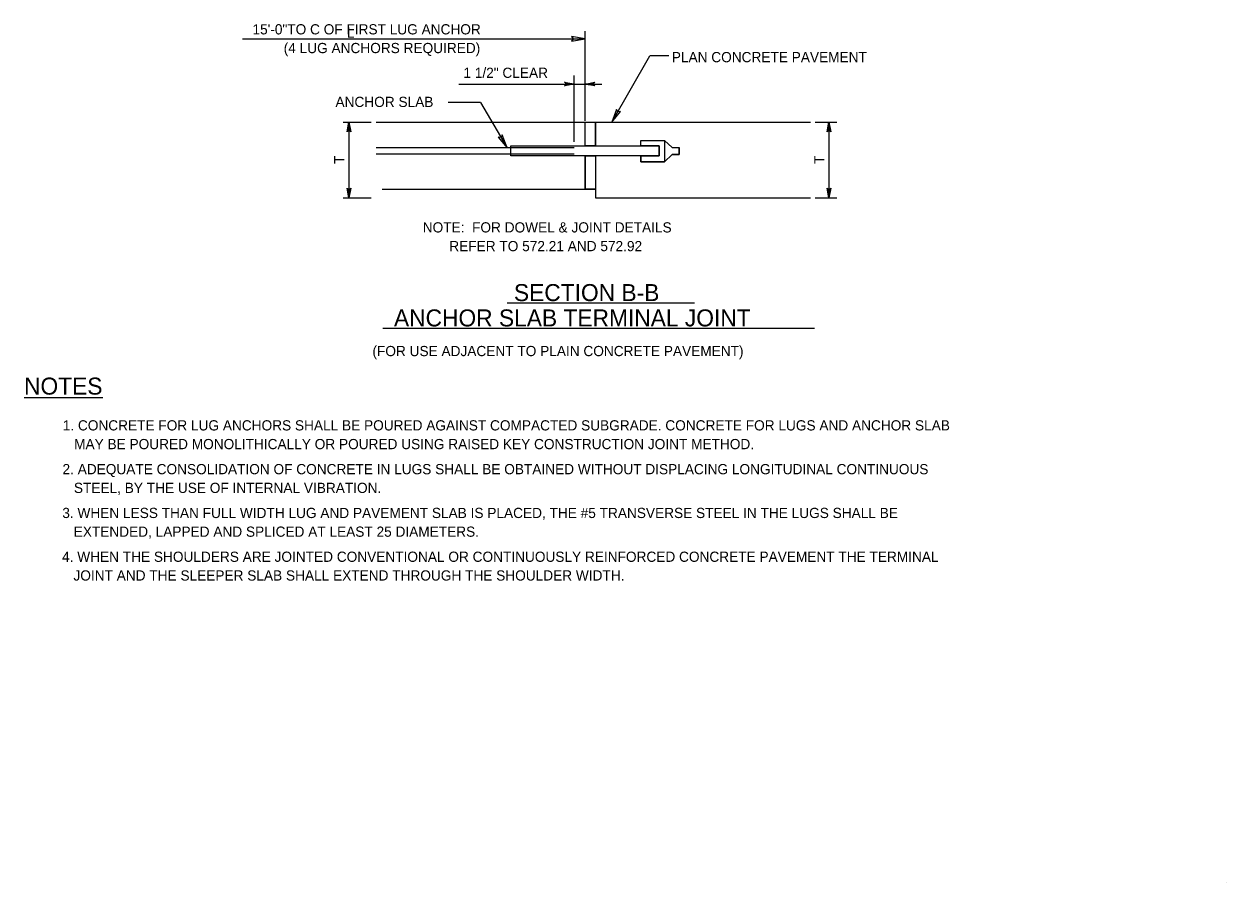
# Model space of a CAD drawing. Extents: x 3.1 to 10.2, y 1.2 to 11.3.
# Drawn here: x 3.1 to 10.16, y 1.24 to 6.28 of the extents above; entities that cross this region are included whole.
import ezdxf

# ---------------------------------------------------------------- set-up
doc = ezdxf.new("R2010")
doc.units = 0
for name, color, linetype in [('DETL-DIMS', 7, 'Continuous'), ('DETL-LINE', 7, 'Continuous'), ('DETL-NOTE', 7, 'Continuous'), ('DETL-TITL', 7, 'Continuous'), ('TTLB-TEXT', 7, 'Continuous')]:
    doc.layers.add(name, color=color, linetype=linetype)

msp = doc.modelspace()

# ---------------------------------------------------------------- linework, layer by layer
at = {"layer": 'DETL-DIMS'}
for p, q in [((6.3939, 5.715), (6.3939, 6.2413)), ((4.3804, 6.1972), (6.3939, 6.1972)), ((6.3939, 6.1972), (6.3141, 6.2105)), ((6.3141, 6.2105), (6.3241, 6.1972)), ((6.3939, 6.1972), (6.3141, 6.2105)), ((6.3141, 6.2105), (6.3241, 6.1972)), ((6.3241, 6.1972), (6.3141, 6.1839)), ((6.3141, 6.1839), (6.3939, 6.1972)), ((6.3241, 6.1972), (6.3141, 6.1839)), ((6.3141, 6.1839), (6.3939, 6.1972)), ((6.5507, 5.7069), (6.7733, 6.0977)), ((6.8851, 6.0977), (6.7733, 6.0977)), ((6.3297, 5.593), (6.3297, 5.9815)), ((5.6524, 5.9317), (6.4911, 5.9317)), ((5.7794, 5.8233), (5.59, 5.8233)), ((5.7794, 5.8233), (5.9351, 5.5578)), ((6.5785, 5.7828), (6.5507, 5.7069)), ((6.5785, 5.7828), (6.5507, 5.7069)), ((6.5507, 5.7069), (6.6017, 5.7697)), ((6.5507, 5.7069), (6.6017, 5.7697)), ((6.5852, 5.7675), (6.5785, 5.7828)), ((6.5852, 5.7675), (6.5785, 5.7828)), ((6.6017, 5.7697), (6.5852, 5.7675)), ((6.6017, 5.7697), (6.5852, 5.7675)), ((4.9721, 5.7069), (5.1367, 5.7069)), ((5.006, 5.7069), (5.006, 5.2638)), ((7.7458, 5.7069), (7.872, 5.7069)), ((7.8262, 5.7069), (7.8262, 5.2638)), ((5.8998, 5.618), (5.8832, 5.6199)), ((5.8832, 5.6199), (5.9351, 5.5578)), ((5.8998, 5.618), (5.8832, 5.6199)), ((5.8832, 5.6199), (5.9351, 5.5578)), ((5.9061, 5.6334), (5.8998, 5.618)), ((5.9061, 5.6334), (5.8998, 5.618)), ((5.9351, 5.5578), (5.9061, 5.6334)), ((5.9351, 5.5578), (5.9061, 5.6334)), ((4.9721, 5.2638), (5.1367, 5.2638)), ((7.7458, 5.2638), (7.872, 5.2638))]:
    msp.add_line(p, q, dxfattribs=at)
for points in [[(6.3297, 5.9317), (6.2732, 5.9211), (6.2776, 5.9241), (6.2798, 5.9279), (6.2804, 5.9317), (6.2798, 5.9355), (6.2776, 5.9393), (6.2732, 5.9423), (6.3297, 5.9317), (6.2776, 5.9393), (6.2798, 5.9355), (6.3297, 5.9317), (6.2804, 5.9317), (6.2798, 5.9279), (6.3297, 5.9317), (6.2776, 5.9241)], [(6.3939, 5.9317), (6.4504, 5.9423), (6.446, 5.9393), (6.4438, 5.9355), (6.4431, 5.9317), (6.4438, 5.9279), (6.446, 5.9241), (6.4504, 5.9211), (6.3939, 5.9317), (6.446, 5.9241), (6.4438, 5.9279), (6.3939, 5.9317), (6.4431, 5.9317), (6.4438, 5.9355), (6.3939, 5.9317), (6.446, 5.9393)], [(5.006, 5.7069), (5.0166, 5.6504), (5.0136, 5.6548), (5.0098, 5.657), (5.006, 5.6577), (5.0023, 5.657), (4.9985, 5.6548), (4.9955, 5.6504), (5.006, 5.7069), (4.9985, 5.6548), (5.0023, 5.657), (5.006, 5.7069), (5.006, 5.6577), (5.0098, 5.657), (5.006, 5.7069), (5.0136, 5.6548)], [(7.8262, 5.7069), (7.8368, 5.6504), (7.8338, 5.6548), (7.83, 5.657), (7.8262, 5.6577), (7.8225, 5.657), (7.8187, 5.6548), (7.8157, 5.6504), (7.8262, 5.7069), (7.8187, 5.6548), (7.8225, 5.657), (7.8262, 5.7069), (7.8262, 5.6577), (7.83, 5.657), (7.8262, 5.7069), (7.8338, 5.6548)], [(5.006, 5.2638), (4.9955, 5.3202), (4.9985, 5.3159), (5.0023, 5.3137), (5.006, 5.313), (5.0098, 5.3137), (5.0136, 5.3159), (5.0166, 5.3202), (5.006, 5.2638), (5.0136, 5.3159), (5.0098, 5.3137), (5.006, 5.2638), (5.006, 5.313), (5.0023, 5.3137), (5.006, 5.2638), (4.9985, 5.3159)], [(7.8262, 5.2638), (7.8157, 5.3202), (7.8187, 5.3159), (7.8225, 5.3137), (7.8262, 5.313), (7.83, 5.3137), (7.8338, 5.3159), (7.8368, 5.3202), (7.8262, 5.2638), (7.8338, 5.3159), (7.83, 5.3137), (7.8262, 5.2638), (7.8262, 5.313), (7.8225, 5.3137), (7.8262, 5.2638), (7.8187, 5.3159)]]:
    msp.add_lwpolyline(points, dxfattribs=at)
at = {"layer": 'DETL-LINE'}
for p, q in [((5.1672, 5.7069), (7.7176, 5.7069)), ((6.3939, 5.5679), (6.3939, 5.7069)), ((6.4543, 5.5679), (6.4543, 5.7069)), ((6.9057, 5.5588), (6.8592, 5.6001)), ((6.3297, 5.5578), (5.1672, 5.5578)), ((6.3297, 5.5196), (5.1672, 5.5196)), ((6.9057, 5.5186), (6.8592, 5.4753)), ((6.3939, 5.5095), (6.3939, 5.3141)), ((6.4543, 5.5095), (6.4543, 5.2638)), ((5.2014, 5.3141), (6.4543, 5.3141)), ((6.4543, 5.2638), (7.7176, 5.2638)), ((3.0979, 4.0898), (3.5598, 4.0898))]:
    msp.add_line(p, q, dxfattribs=at)
for points in [[(6.3939, 5.7069), (6.4543, 5.7069), (6.4543, 5.5679), (6.3939, 5.5679)], [(6.7202, 5.5679), (6.7202, 5.6001), (6.8592, 5.6001), (6.9057, 5.5588), (6.9458, 5.5588), (6.9458, 5.5186), (6.9057, 5.5186), (6.8592, 5.4753), (6.7202, 5.4753), (6.7202, 5.5095), (6.8289, 5.5095), (6.8289, 5.5679)], [(5.9568, 5.5679), (6.8289, 5.5679), (6.8289, 5.5095), (5.9568, 5.5095)], [(6.3939, 5.5095), (6.4543, 5.5095), (6.4543, 5.3141), (6.3939, 5.3141)]]:
    msp.add_lwpolyline(points, close=True, dxfattribs=at)
for points in [[(6.7202, 5.5679), (6.7202, 5.6001), (6.8592, 5.6001), (6.8592, 5.4753)], [(5.9568, 5.5679), (6.8289, 5.5679), (6.8289, 5.5095), (5.9568, 5.5095), (5.9568, 5.5679)], [(6.9057, 5.5588), (6.9458, 5.5588), (6.9458, 5.5186)], [(6.9057, 5.5186), (6.9458, 5.5186), (6.9458, 5.5588)], [(6.7202, 5.5095), (6.7202, 5.4753), (6.8592, 5.4753)]]:
    msp.add_lwpolyline(points, dxfattribs=at)
at = {"layer": 'DETL-TITL'}
for p, q in [((5.935, 4.6452), (7.0361, 4.6452)), ((5.2051, 4.4964), (7.742, 4.4964))]:
    msp.add_line(p, q, dxfattribs=at)
at = {"layer": 'TTLB-TEXT'}
msp.add_line((10.1642, 1.2378), (10.1642, 1.2378), dxfattribs=at)

# ---------------------------------------------------------------- texts
at = {"layer": 'DETL-NOTE'}
for s, height, p in [('15\'-0"TO C OF FIRST LUG ANCHOR', 0.06, (4.4399, 6.2232)), ('(4 LUG ANCHORS REQUIRED)', 0.06, (4.6232, 6.1132)), ('PLAN CONCRETE PAVEMENT', 0.06, (6.9031, 6.0598)), ('1 1/2" CLEAR', 0.06, (5.6789, 5.9678)), ('ANCHOR SLAB', 0.06, (4.9274, 5.7968)), ('NOTE:  FOR DOWEL & JOINT DETAILS', 0.06, (5.44, 5.0595)), ('       REFER TO 572.21 AND 572.92', 0.06, (5.44, 4.9495)), ('(FOR USE ADJACENT TO PLAIN CONCRETE PAVEMENT)', 0.06, (5.1445, 4.3329)), ('NOTES', 0.1, (3.0979, 4.1069)), ('1. CONCRETE FOR LUG ANCHORS SHALL BE POURED AGAINST COMPACTED SUBGRADE. CONCRETE FOR LUGS AND ANCHOR SLAB ', 0.06, (3.3252, 3.8963)), ('   MAY BE POURED MONOLITHICALLY OR POURED USING RAISED KEY CONSTRUCTION JOINT METHOD.', 0.06, (3.3252, 3.7863)), ('2. ADEQUATE CONSOLIDATION OF CONCRETE IN LUGS SHALL BE OBTAINED WITHOUT DISPLACING LONGITUDINAL CONTINUOUS ', 0.06, (3.3239, 3.639)), ('   STEEL, BY THE USE OF INTERNAL VIBRATION.', 0.06, (3.3239, 3.529)), ('3. WHEN LESS THAN FULL WIDTH LUG AND PAVEMENT SLAB IS PLACED, THE #5 TRANSVERSE STEEL IN THE LUGS SHALL BE', 0.06, (3.3226, 3.3817)), ('   EXTENDED, LAPPED AND SPLICED AT LEAST 25 DIAMETERS.', 0.06, (3.3226, 3.2717)), ('4. WHEN THE SHOULDERS ARE JOINTED CONVENTIONAL OR CONTINUOUSLY REINFORCED CONCRETE PAVEMENT THE TERMINAL', 0.06, (3.3213, 3.1244)), ('   JOINT AND THE SLEEPER SLAB SHALL EXTEND THROUGH THE SHOULDER WIDTH.', 0.06, (3.3213, 3.0144))]:
    msp.add_text(s, height=height, dxfattribs=at).set_placement(p)
for s, rotation, p in [('L', 359.99999, (4.9938, 6.204)), ('T', 90, (4.9795, 5.4626)), ('T', 90, (7.7997, 5.4626))]:
    msp.add_text(s, height=0.06, rotation=rotation, dxfattribs=at).set_placement(p)
at = {"layer": 'DETL-TITL'}
for s, p in [('SECTION B-B', (5.9756, 4.6563)), ('ANCHOR SLAB TERMINAL JOINT', (5.2709, 4.5075))]:
    msp.add_text(s, height=0.1, dxfattribs=at).set_placement(p)

doc.saveas('drawing.dxf')
